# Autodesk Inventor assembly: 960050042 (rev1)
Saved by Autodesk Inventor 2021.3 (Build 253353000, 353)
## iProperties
Created: 2023-03
Part Number: 960050042 (rev1)
Document SubType Name: Assembly
Designer: AdminForWorker
Title: 960050042 (rev1) v2
Author: AdminForWorker
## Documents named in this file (2)
- z:\worker\convert-fusion-r08-cosv3\tmp\job-1\3553\output\files\82b4d9ad-b575-4129-b9ca-4964d6b72adf\960050042 (rev1) v2_1.iam
- z:\worker\convert-fusion-r08-cosv3\tmp\job-1\3553\output\files\82b4d9ad-b575-4129-b9ca-4964d6b72adf\960050042 (rev1).ipt
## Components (1 placed, 1 different names)
1. 960050042 (rev1):1
